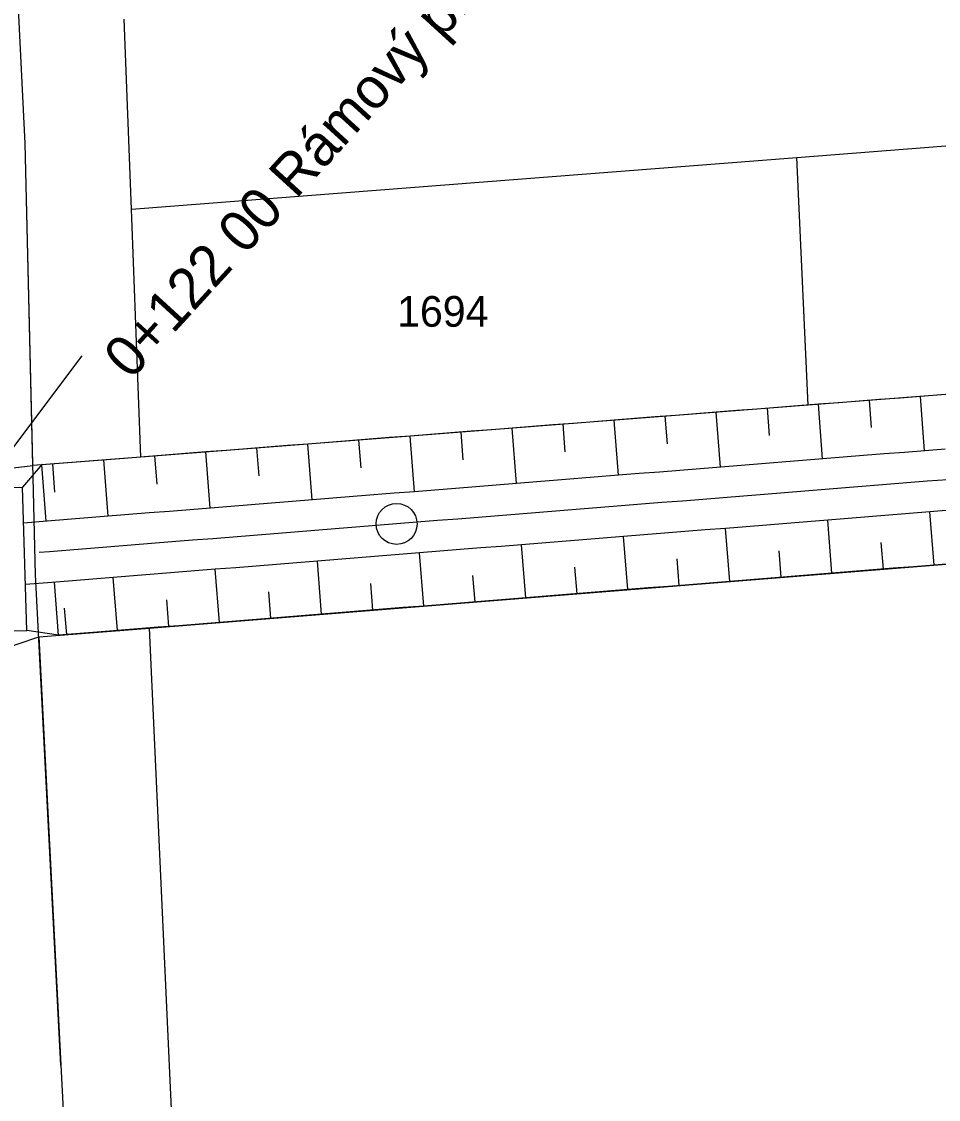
# Model space of a CAD drawing. Extents: x -583721 to -583071, y -1166145 to -1165065.
# Drawn here: x -583204 to -583159.2, y -1166024.9 to -1165972.3 of the extents above; entities that cross this region are included whole.
import ezdxf

# ---------------------------------------------------------------- set-up
doc = ezdxf.new("R2010")
doc.units = 0
for name, color, linetype in [('01_DOPRAVA', 7, 'Continuous'), ('14', 7, 'Continuous'), ('21', 7, 'Continuous'), ('KOTY', 7, 'Continuous'), ('Parcelní čísla', 7, 'Continuous'), ('Popis cest', 7, 'Continuous'), ('TISK', 7, 'Continuous'), ('Trojúhelniky', 7, 'Continuous')]:
    doc.layers.add(name, color=color, linetype=linetype)

msp = doc.modelspace()

# ---------------------------------------------------------------- linework, layer by layer
at = {"layer": '01_DOPRAVA'}
for p, q in [((-583198.6, -1165981.46), (-583198.95, -1165972.17)), ((-583166.11, -1165978.93), (-583106.39, -1165974.27)), ((-583198.6, -1165981.46), (-583166.11, -1165978.93)), ((-583165.55, -1165991.02), (-583166.11, -1165978.93)), ((-583198.14, -1165993.56), (-583198.6, -1165981.46)), ((-583094.47, -1165985.62), (-583165.55, -1165991.02)), ((-583165.55, -1165991.02), (-583198.14, -1165993.56)), ((-583197.71, -1166001.91), (-583089.61, -1165993.23)), ((-583198.14, -1165993.56), (-583203.41, -1165993.97)), ((-583203.12, -1166002.34), (-583197.71, -1166001.91)), ((-583215.5, -1166006.52), (-583203.12, -1166002.34))]:
    msp.add_line(p, q, dxfattribs=at)
for points in [[(-583228.69, -1165666.2), (-583226.21, -1165672.99), (-583225.84, -1165679.92), (-583220.97, -1165796.08), (-583216.51, -1165909.44), (-583213.19, -1165995.13), (-583203.41, -1165993.97)], [(-583203.41, -1165993.97), (-583203.79, -1165978.24), (-583205.99, -1165934.1), (-583206.83, -1165909.26), (-583206.76, -1165905.62)], [(-583192.95, -1166104.36), (-583195.91, -1166040.97), (-583196.69, -1166024.36), (-583197.71, -1166001.91)], [(-583203.12, -1166002.34), (-583201.46, -1166034.65), (-583199.85, -1166072.99), (-583198.37, -1166093.85), (-583197.875, -1166107.776)]]:
    msp.add_lwpolyline(points, dxfattribs=at)
at = {"layer": '14'}
for p, q in [((-583162.461, -1165992.122), (-583162.562, -1165990.793)), ((-583159.868, -1165993.252), (-583160.069, -1165990.604)), ((-583169.83, -1165994.052), (-583170.04, -1165991.37)), ((-583167.443, -1165992.514), (-583167.547, -1165991.176)), ((-583164.85, -1165993.652), (-583165.055, -1165990.982)), ((-583177.412, -1165993.302), (-583177.517, -1165991.953)), ((-583174.814, -1165994.452), (-583175.024, -1165991.758)), ((-583172.427, -1165992.908), (-583172.532, -1165991.564)), ((-583182.396, -1165993.697), (-583182.502, -1165992.341)), ((-583179.798, -1165994.852), (-583180.009, -1165992.147)), ((-583189.766, -1165995.653), (-583189.979, -1165992.924)), ((-583187.38, -1165994.091), (-583187.487, -1165992.73)), ((-583184.782, -1165995.252), (-583184.994, -1165992.535)), ((-583197.349, -1165994.88), (-583197.456, -1165993.507)), ((-583194.75, -1165996.053), (-583194.964, -1165993.312)), ((-583192.365, -1165994.485), (-583192.471, -1165993.118)), ((-583202.756, -1165996.696), (-583202.971, -1165993.936)), ((-583202.334, -1165995.274), (-583202.441, -1165993.895)), ((-583199.735, -1165996.453), (-583199.949, -1165993.701)), ((-583164.393, -1165999.235), (-583164.601, -1165996.641)), ((-583159.409, -1165998.835), (-583159.617, -1165996.241)), ((-583169.376, -1165999.635), (-583169.585, -1165997.042)), ((-583174.36, -1166000.035), (-583174.569, -1165997.442)), ((-583162.005, -1165997.738), (-583161.901, -1165999.035)), ((-583184.328, -1166000.836), (-583184.537, -1165998.242)), ((-583179.344, -1166000.435), (-583179.553, -1165997.842)), ((-583166.989, -1165998.138), (-583166.885, -1165999.435)), ((-583189.312, -1166001.236), (-583189.521, -1165998.642)), ((-583171.973, -1165998.538), (-583171.868, -1165999.835)), ((-583194.296, -1166001.636), (-583194.505, -1165999.043)), ((-583176.957, -1165998.939), (-583176.852, -1166000.235)), ((-583202.155, -1166002.263), (-583202.361, -1165999.673)), ((-583199.28, -1166002.035), (-583199.487, -1165999.443)), ((-583186.924, -1165999.739), (-583186.82, -1166001.036)), ((-583181.94, -1165999.339), (-583181.836, -1166000.635)), ((-583191.908, -1166000.139), (-583191.804, -1166001.436)), ((-583196.892, -1166000.539), (-583196.788, -1166001.836)), ((-583201.875, -1166000.938), (-583201.772, -1166002.233))]:
    msp.add_line(p, q, dxfattribs=at)
at = {"layer": '21'}
for p, q in [((-583204.87, -1165995.056), (-583203.921, -1165995.027)), ((-583203.705, -1166002.024), (-583203.921, -1165995.027)), ((-583204.655, -1166002.053), (-583203.705, -1166002.024))]:
    msp.add_line(p, q, dxfattribs=at)
for points in [[(-583159.072, -1165990.528), (-583160.069, -1165990.604), (-583161.067, -1165990.679), (-583162.064, -1165990.755), (-583163.061, -1165990.831), (-583164.058, -1165990.907), (-583165.055, -1165990.982), (-583166.052, -1165991.059), (-583167.049, -1165991.137), (-583168.046, -1165991.215), (-583169.043, -1165991.292), (-583170.04, -1165991.37), (-583171.037, -1165991.448), (-583172.034, -1165991.525), (-583173.031, -1165991.603), (-583174.028, -1165991.681), (-583175.025, -1165991.758), (-583176.022, -1165991.836), (-583177.019, -1165991.914), (-583178.016, -1165991.992), (-583179.013, -1165992.069), (-583180.01, -1165992.147), (-583181.007, -1165992.225), (-583182.004, -1165992.302), (-583183.001, -1165992.38), (-583183.998, -1165992.458), (-583184.995, -1165992.535), (-583185.992, -1165992.613), (-583186.989, -1165992.691), (-583187.986, -1165992.769), (-583188.983, -1165992.846), (-583189.98, -1165992.924), (-583190.977, -1165993.002), (-583191.974, -1165993.079), (-583192.971, -1165993.157), (-583193.968, -1165993.235), (-583194.965, -1165993.313), (-583195.962, -1165993.39), (-583196.959, -1165993.468), (-583197.956, -1165993.546), (-583198.953, -1165993.623), (-583202.971, -1165993.936)], [(-583158.86, -1165993.171), (-583159.857, -1165993.251), (-583160.854, -1165993.331), (-583161.85, -1165993.411), (-583162.847, -1165993.491), (-583163.844, -1165993.571), (-583164.841, -1165993.651), (-583165.838, -1165993.731), (-583166.834, -1165993.811), (-583167.831, -1165993.891), (-583168.828, -1165993.971), (-583169.825, -1165994.051), (-583170.822, -1165994.131), (-583171.818, -1165994.211), (-583172.815, -1165994.291), (-583173.812, -1165994.371), (-583174.809, -1165994.451), (-583175.806, -1165994.532), (-583176.802, -1165994.612), (-583177.799, -1165994.692), (-583178.796, -1165994.772), (-583179.793, -1165994.852), (-583180.79, -1165994.932), (-583181.786, -1165995.012), (-583182.783, -1165995.092), (-583183.78, -1165995.172), (-583184.777, -1165995.252), (-583185.773, -1165995.332), (-583186.77, -1165995.412), (-583187.767, -1165995.492), (-583188.764, -1165995.572), (-583189.761, -1165995.652), (-583190.757, -1165995.732), (-583191.754, -1165995.812), (-583192.751, -1165995.892), (-583193.748, -1165995.972), (-583194.745, -1165996.052), (-583195.741, -1165996.132), (-583196.738, -1165996.212), (-583197.735, -1165996.292), (-583198.732, -1165996.372), (-583199.729, -1165996.452), (-583200.725, -1165996.532), (-583201.722, -1165996.613), (-583202.719, -1165996.693), (-583203.867, -1165996.785)], [(-583202.95, -1165993.912), (-583203.921, -1165995.027)], [(-583158.62, -1165996.161), (-583159.617, -1165996.241), (-583160.614, -1165996.321), (-583161.61, -1165996.401), (-583162.607, -1165996.481), (-583163.604, -1165996.561), (-583164.601, -1165996.641), (-583165.598, -1165996.722), (-583166.594, -1165996.802), (-583167.591, -1165996.882), (-583168.588, -1165996.962), (-583169.585, -1165997.042), (-583170.582, -1165997.122), (-583171.578, -1165997.202), (-583172.575, -1165997.282), (-583173.572, -1165997.362), (-583174.569, -1165997.442), (-583175.565, -1165997.522), (-583176.562, -1165997.602), (-583177.559, -1165997.682), (-583178.556, -1165997.762), (-583179.553, -1165997.842), (-583180.549, -1165997.922), (-583181.546, -1165998.002), (-583182.543, -1165998.082), (-583183.54, -1165998.162), (-583184.537, -1165998.242), (-583185.533, -1165998.322), (-583186.53, -1165998.402), (-583187.527, -1165998.482), (-583188.524, -1165998.562), (-583189.521, -1165998.642), (-583190.517, -1165998.722), (-583191.514, -1165998.803), (-583192.511, -1165998.883), (-583193.508, -1165998.963), (-583194.505, -1165999.043), (-583195.501, -1165999.123), (-583196.498, -1165999.203), (-583197.495, -1165999.283), (-583198.492, -1165999.363), (-583199.488, -1165999.443), (-583200.485, -1165999.523), (-583201.482, -1165999.603), (-583202.479, -1165999.683), (-583203.774, -1165999.787)], [(-583158.412, -1165998.755), (-583159.409, -1165998.835), (-583160.405, -1165998.915), (-583161.402, -1165998.995), (-583162.399, -1165999.075), (-583163.396, -1165999.155), (-583164.393, -1165999.235), (-583165.389, -1165999.315), (-583166.386, -1165999.395), (-583167.383, -1165999.475), (-583168.38, -1165999.555), (-583169.376, -1165999.635), (-583170.373, -1165999.715), (-583171.37, -1165999.795), (-583172.367, -1165999.875), (-583173.364, -1165999.955), (-583174.36, -1166000.035), (-583175.357, -1166000.115), (-583176.354, -1166000.195), (-583177.351, -1166000.275), (-583178.348, -1166000.355), (-583179.344, -1166000.435), (-583180.341, -1166000.515), (-583181.338, -1166000.595), (-583182.335, -1166000.675), (-583183.332, -1166000.755), (-583184.328, -1166000.836), (-583185.325, -1166000.916), (-583186.322, -1166000.996), (-583187.319, -1166001.076), (-583188.316, -1166001.156), (-583189.312, -1166001.236), (-583190.309, -1166001.316), (-583191.306, -1166001.396), (-583192.303, -1166001.476), (-583193.299, -1166001.556), (-583194.296, -1166001.636), (-583195.293, -1166001.716), (-583196.29, -1166001.796), (-583197.287, -1166001.876), (-583198.283, -1166001.956), (-583199.28, -1166002.035), (-583200.277, -1166002.114), (-583202.155, -1166002.263)], [(-583202.155, -1166002.263), (-583203.705, -1166002.024)]]:
    msp.add_lwpolyline(points, dxfattribs=at)
at = {"layer": 'KOTY'}
msp.add_lwpolyline([(-583158.74, -1165994.666), (-583159.737, -1165994.746), (-583160.734, -1165994.826), (-583161.73, -1165994.906), (-583162.727, -1165994.986), (-583163.724, -1165995.066), (-583164.721, -1165995.146), (-583165.718, -1165995.226), (-583166.714, -1165995.306), (-583167.711, -1165995.386), (-583168.708, -1165995.466), (-583169.705, -1165995.546), (-583170.702, -1165995.627), (-583171.698, -1165995.707), (-583172.695, -1165995.787), (-583173.692, -1165995.867), (-583174.689, -1165995.947), (-583175.686, -1165996.027), (-583176.682, -1165996.107), (-583177.679, -1165996.187), (-583178.676, -1165996.267), (-583179.673, -1165996.347), (-583180.669, -1165996.427), (-583181.666, -1165996.507), (-583182.663, -1165996.587), (-583183.66, -1165996.667), (-583184.657, -1165996.747), (-583185.653, -1165996.827), (-583186.65, -1165996.907), (-583187.647, -1165996.987), (-583188.644, -1165997.067), (-583189.641, -1165997.147), (-583190.637, -1165997.227), (-583191.634, -1165997.307), (-583192.631, -1165997.387), (-583193.628, -1165997.467), (-583194.625, -1165997.547), (-583195.621, -1165997.627), (-583196.618, -1165997.708), (-583197.615, -1165997.788), (-583198.612, -1165997.868), (-583199.609, -1165997.948), (-583200.605, -1165998.028), (-583201.602, -1165998.108), (-583202.599, -1165998.188), (-583203.097, -1165998.228)], dxfattribs=at)
at = {"layer": 'Popis cest'}
msp.add_lwpolyline([(-583202.046, -1166023.279), (-583203.28, -1165999.31), (-583203.79, -1165978.24), (-583205.99, -1165934.1), (-583206.83, -1165909.26), (-583206.76, -1165905.62), (-583208.9, -1165862.71), (-583209.34, -1165848.45), (-583210.45, -1165834.4), (-583212.79, -1165765.14), (-583213.22, -1165730.9), (-583214.43, -1165703.46)], dxfattribs=at)
at = {"layer": 'TISK'}
msp.add_lwpolyline([(-583208.551, -1165998.666), (-583201.01, -1165988.612)], dxfattribs=at)
at = {"layer": 'Trojúhelniky'}
msp.add_circle((-583185.653, -1165996.827), 1, dxfattribs=at)
msp.add_circle((-583185.653, -1165996.827), 1, dxfattribs=at)

# ---------------------------------------------------------------- texts
at = {"layer": 'Parcelní čísla'}
msp.add_text('1694', height=1.5, dxfattribs=at).set_placement((-583185.627, -1165987.196))
at = {"layer": 'TISK'}
msp.add_text('0+122 00 Rámový propustek IZE 141 1000x2000', height=2, rotation=47.6254, dxfattribs=at).set_placement((-583198.632, -1165989.836))

doc.saveas('drawing.dxf')
